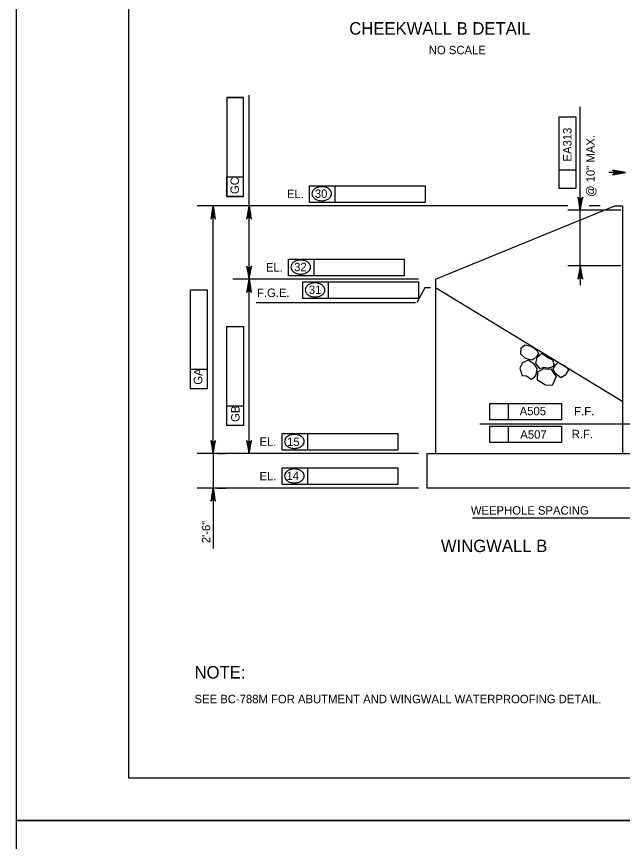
# Model space of a CAD drawing. Extents: x 638340 to 640242, y 295465 to 298435.
# Drawn here: x 638435.5 to 638651, y 296646 to 296939.5 of the extents above; entities that cross this region are included whole.
import ezdxf

# ---------------------------------------------------------------- set-up
doc = ezdxf.new("R2010")
doc.units = 0
for name, color, linetype in [('1', 7, 'Continuous'), ('2', 7, 'Continuous'), ('3', 7, 'Continuous'), ('4', 7, 'Continuous'), ('Level 10', 7, 'Continuous'), ('Level 3', 7, 'Continuous'), ('Level 4', 7, 'Continuous'), ('PLT-BNDY', 7, 'Continuous')]:
    doc.layers.add(name, color=color, linetype=linetype)

# ---------------------------------------------------------------- blocks, each defined once
blk = doc.blocks.new('ROCK')
at = {"layer": '4'}
for points in [[(2.36725, 1.088), (2.2065, 0.82625), (2.378625, 0.506625), (2.66975, 0.3095), (3.128875, 0.403375), (3.48475, 0.6775), (3.4915, 1.123375), (3.25625, 1.36725), (2.783625, 1.308375)], [(1.10175, -0.02725), (1.4015, -0.159125), (1.78825, -0.148875), (1.980875, -0.266), (2.343375, 0.09475), (2.27875, 0.5505), (1.969375, 0.883), (1.4225, 0.553625), (1.152875, 0.479), (1.0105, 0.082)], [(0.74675, 0.359875), (0.882, 0.16), (1.072875, -0.144), (0.892, -0.457375), (0.448125, -0.758625), (0.1, -0.49325), (-0.095, -0.146375), (0.202875, 0.1025), (0.579125, 0.219875)], [(2.231375, -0.71725), (2.2025, -0.266375), (2.45475, 0.037125), (2.9085, 0.28875), (3.2995, 0.047625), (3.46875, -0.344), (3.231625, -0.855), (2.92, -0.860375), (2.5765, -1.054625), (2.340375, -0.904375)], [(1.2085, -0.192875), (0.778375, -0.737625), (1.008375, -1.391375), (1.48725, -1.396875), (2.09825, -1.106625), (2.133375, -0.486375), (1.723125, -0.203375), (1.37425, -0.239875)]]:
    blk.add_lwpolyline(points, close=True, dxfattribs=at)
blk = doc.blocks.new('V')
at = {"layer": '1'}
blk.add_line((0, 0), (0, 0), dxfattribs=at)

msp = doc.modelspace()

# ---------------------------------------------------------------- linework, layer by layer
at = {"layer": '2'}
for p, q in [((638475.46, 296668.46), (638475.46, 297232.46)), ((639261.46, 296668.46), (638475.46, 296668.46))]:
    msp.add_line(p, q, dxfattribs=at)
at = {"layer": 'Level 10'}
for p, q in [((638584.47, 296845.97), (638648.28, 296872.06)), ((638648.28, 296872.06), (638650.94, 296872.06)), ((638650.94, 296872.06), (638650.94, 296783.96)), ((638584.47, 296845.97), (638584.47, 296783.96)), ((638651.16, 296802.37), (638584.47, 296842.9)), ((638581.4, 296783.96), (638729.24, 296783.96)), ((638581.4, 296783.96), (638581.4, 296771.68)), ((638961.9, 296771.68), (638581.4, 296771.68))]:
    msp.add_line(p, q, dxfattribs=at)
at = {"layer": 'Level 3'}
for p, q in [((638510.32, 296910.64), (638510.32, 296875.4)), ((638516.22, 296910.64), (638510.32, 296910.64)), ((638510.32, 296910.64), (638516.22, 296910.64)), ((638516.22, 296882.24), (638516.22, 296910.64)), ((638516.22, 296903.81), (638516.22, 296910.64)), ((638518.18, 296845.97), (638518.18, 296911.47)), ((638635.97, 296870.53), (638635.97, 296907.31)), ((638628.45, 296878.25), (638628.45, 296903.74)), ((638628.45, 296903.74), (638634.35, 296903.74)), ((638634.35, 296903.74), (638634.35, 296878.25)), ((638634.35, 296884.83), (638628.45, 296884.83)), ((638652.09, 296883.97), (638646.18, 296883.97)), ((638510.32, 296875.4), (638510.32, 296882.24)), ((638516.22, 296882.24), (638510.32, 296882.24)), ((638516.22, 296875.4), (638516.22, 296882.24)), ((638539.65, 296879.24), (638548.81, 296879.24)), ((638539.65, 296873.34), (638539.65, 296879.24)), ((638548.81, 296873.34), (638548.81, 296879.24)), ((638548.81, 296879.24), (638580.78, 296879.24)), ((638580.78, 296879.24), (638580.78, 296873.34)), ((638634.35, 296878.25), (638628.45, 296878.25)), ((638510.32, 296875.4), (638516.22, 296875.4)), ((638516.22, 296875.4), (638510.32, 296875.4)), ((638635.97, 296873.47), (638635.97, 296876.42)), ((638631.58, 296872.06), (638499.66, 296872.06)), ((638506.51, 296872.06), (638501, 296872.06)), ((638511.74, 296872.06), (638501, 296872.06)), ((638505.42, 296783.96), (638505.42, 296872.06)), ((638520.64, 296872.06), (638513.76, 296872.06)), ((638580.78, 296873.34), (638539.65, 296873.34)), ((638643.03, 296872.06), (638639.11, 296872.06)), ((638650.4, 296870.53), (638631.55, 296870.53)), ((638635.97, 296849.77), (638635.97, 296870.53)), ((638532.17, 296853.14), (638541.32, 296853.14)), ((638532.17, 296847.25), (638532.17, 296853.14)), ((638541.32, 296847.25), (638541.32, 296853.14)), ((638541.32, 296853.14), (638573.3, 296853.14)), ((638573.3, 296853.14), (638573.3, 296847.25)), ((638650.4, 296850.7), (638631.55, 296850.7)), ((638635.97, 296849.77), (638635.97, 296843.88)), ((638578.42, 296845.97), (638512.41, 296845.97)), ((638523.52, 296845.97), (638513.76, 296845.97)), ((638518.18, 296783.96), (638518.18, 296845.97)), ((638573.3, 296847.25), (638532.17, 296847.25)), ((638537.28, 296845.01), (638546.43, 296845.01)), ((638537.28, 296839.12), (638537.28, 296845.01)), ((638546.43, 296839.12), (638546.43, 296845.01)), ((638546.43, 296845.01), (638578.41, 296845.01)), ((638578.41, 296845.01), (638578.41, 296839.12)), ((638497.38, 296842.24), (638503.28, 296842.24)), ((638497.38, 296813.84), (638497.38, 296842.24)), ((638503.28, 296842.24), (638503.28, 296807.01)), ((638580.65, 296842.9), (638577.88, 296837.71)), ((638578.41, 296839.12), (638537.28, 296839.12)), ((638520.66, 296837.71), (638577.35, 296837.71)), ((638510.28, 296829.2), (638516.17, 296829.2)), ((638510.28, 296800.79), (638510.28, 296829.2)), ((638516.17, 296829.2), (638516.17, 296793.96)), ((638497.38, 296807.01), (638497.38, 296813.84)), ((638503.28, 296813.84), (638497.38, 296813.84)), ((638503.28, 296807.01), (638497.38, 296807.01)), ((638510.28, 296793.96), (638510.28, 296800.79)), ((638516.17, 296800.79), (638510.28, 296800.79)), ((638603.82, 296801.82), (638629.31, 296801.82)), ((638603.82, 296795.93), (638603.82, 296801.82)), ((638610.4, 296795.93), (638610.4, 296801.82)), ((638629.31, 296801.82), (638629.31, 296795.93)), ((638629.31, 296795.93), (638603.82, 296795.93)), ((638516.17, 296793.96), (638510.28, 296793.96)), ((638600.3, 296794.53), (638662, 296794.53)), ((638603.82, 296787.86), (638603.82, 296793.76)), ((638603.82, 296793.76), (638629.31, 296793.76)), ((638610.4, 296787.86), (638610.4, 296793.76)), ((638629.31, 296793.76), (638629.31, 296787.86)), ((638529.91, 296791.13), (638539.07, 296791.13)), ((638529.91, 296785.23), (638529.91, 296791.13)), ((638539.07, 296785.23), (638539.07, 296791.13)), ((638539.07, 296791.13), (638571.04, 296791.13)), ((638571.04, 296791.13), (638571.04, 296785.23)), ((638629.31, 296787.86), (638603.82, 296787.86)), ((638578.42, 296783.96), (638499.66, 296783.96)), ((638506.51, 296783.96), (638501, 296783.96)), ((638506.98, 296783.96), (638501, 296783.96)), ((638511.74, 296783.96), (638501, 296783.96)), ((638505.42, 296783.96), (638505.42, 296771.68)), ((638506.89, 296783.96), (638509.84, 296783.96)), ((638571.04, 296785.23), (638529.91, 296785.23)), ((638529.91, 296772.96), (638529.91, 296778.85)), ((638529.91, 296778.85), (638539.07, 296778.85)), ((638539.07, 296772.96), (638539.07, 296778.85)), ((638539.07, 296778.85), (638571.04, 296778.85)), ((638571.04, 296778.85), (638571.04, 296772.96)), ((638578.42, 296771.68), (638499.66, 296771.68)), ((638505.42, 296771.68), (638505.42, 296750.18)), ((638506.89, 296771.68), (638509.84, 296771.68)), ((638571.04, 296772.96), (638529.91, 296772.96)), ((638883.14, 296760.94), (638597.64, 296760.94))]:
    msp.add_line(p, q, dxfattribs=at)
for points in [[(638652.09, 296883.97), (638647.44, 296884.84), (638647.8, 296884.6), (638647.98, 296884.29), (638648.03, 296883.97), (638647.98, 296883.66), (638647.8, 296883.35), (638647.44, 296883.1), (638652.09, 296883.97), (638647.8, 296883.35), (638647.98, 296883.66), (638652.09, 296883.97), (638648.03, 296883.97), (638647.98, 296884.29), (638652.09, 296883.97), (638647.8, 296884.6)], [(638635.97, 296870.53), (638636.84, 296875.18), (638636.6, 296874.82), (638636.28, 296874.64), (638635.97, 296874.58), (638635.66, 296874.64), (638635.35, 296874.82), (638635.1, 296875.18), (638635.97, 296870.53), (638635.35, 296874.82), (638635.66, 296874.64), (638635.97, 296870.53), (638635.97, 296874.58), (638636.28, 296874.64), (638635.97, 296870.53), (638636.6, 296874.82)], [(638505.42, 296872.06), (638504.55, 296867.41), (638504.8, 296867.77), (638505.11, 296867.95), (638505.42, 296868.01), (638505.73, 296867.95), (638506.04, 296867.77), (638506.29, 296867.41), (638505.42, 296872.06), (638506.04, 296867.77), (638505.73, 296867.95), (638505.42, 296872.06), (638505.42, 296868.01), (638505.11, 296867.95), (638505.42, 296872.06), (638504.8, 296867.77)], [(638518.18, 296872.06), (638517.31, 296867.41), (638517.56, 296867.77), (638517.87, 296867.95), (638518.18, 296868.01), (638518.49, 296867.95), (638518.8, 296867.77), (638519.05, 296867.41), (638518.18, 296872.06), (638518.8, 296867.77), (638518.49, 296867.95), (638518.18, 296872.06), (638518.18, 296868.01), (638517.87, 296867.95), (638518.18, 296872.06), (638517.56, 296867.77)], [(638518.18, 296845.97), (638519.05, 296850.62), (638518.8, 296850.26), (638518.49, 296850.08), (638518.18, 296850.02), (638517.87, 296850.08), (638517.56, 296850.26), (638517.31, 296850.62), (638518.18, 296845.97), (638517.56, 296850.26), (638517.87, 296850.08), (638518.18, 296845.97), (638518.18, 296850.02), (638518.49, 296850.08), (638518.18, 296845.97), (638518.8, 296850.26)], [(638635.97, 296850.7), (638635.1, 296846.05), (638635.35, 296846.41), (638635.66, 296846.59), (638635.97, 296846.64), (638636.28, 296846.59), (638636.6, 296846.41), (638636.84, 296846.05), (638635.97, 296850.7), (638636.6, 296846.41), (638636.28, 296846.59), (638635.97, 296850.7), (638635.97, 296846.64), (638635.66, 296846.59), (638635.97, 296850.7), (638635.35, 296846.41)], [(638518.18, 296845.97), (638517.31, 296841.32), (638517.56, 296841.67), (638517.87, 296841.86), (638518.18, 296841.91), (638518.49, 296841.86), (638518.8, 296841.67), (638519.05, 296841.32), (638518.18, 296845.97), (638518.8, 296841.67), (638518.49, 296841.86), (638518.18, 296845.97), (638518.18, 296841.91), (638517.87, 296841.86), (638518.18, 296845.97), (638517.56, 296841.67)], [(638505.42, 296783.96), (638506.29, 296788.61), (638506.04, 296788.25), (638505.73, 296788.06), (638505.42, 296788.01), (638505.11, 296788.06), (638504.8, 296788.25), (638504.55, 296788.61), (638505.42, 296783.96), (638504.8, 296788.25), (638505.11, 296788.06), (638505.42, 296783.96), (638505.42, 296788.01), (638505.73, 296788.06), (638505.42, 296783.96), (638506.04, 296788.25)], [(638518.18, 296783.96), (638519.05, 296788.61), (638518.8, 296788.25), (638518.49, 296788.06), (638518.18, 296788.01), (638517.87, 296788.06), (638517.56, 296788.25), (638517.31, 296788.61), (638518.18, 296783.96), (638517.56, 296788.25), (638517.87, 296788.06), (638518.18, 296783.96), (638518.18, 296788.01), (638518.49, 296788.06), (638518.18, 296783.96), (638518.8, 296788.25)], [(638505.42, 296771.68), (638504.55, 296767.03), (638504.8, 296767.38), (638505.11, 296767.57), (638505.42, 296767.62), (638505.73, 296767.57), (638506.04, 296767.38), (638506.29, 296767.03), (638505.42, 296771.68), (638506.04, 296767.38), (638505.73, 296767.57), (638505.42, 296771.68), (638505.42, 296767.62), (638505.11, 296767.57), (638505.42, 296771.68), (638504.8, 296767.38)]]:
    msp.add_lwpolyline(points, dxfattribs=at)
for points in [[(638649.12, 296884.46), (638649.12, 296883.48), (638652.07, 296883.97)], [(638505.91, 296869.12), (638504.93, 296869.12), (638505.42, 296872.06)], [(638518.67, 296869.12), (638517.69, 296869.12), (638518.18, 296872.06)], [(638636.47, 296873.47), (638635.48, 296873.47), (638635.97, 296870.53)], [(638518.67, 296848.92), (638517.69, 296848.92), (638518.18, 296845.97)], [(638518.67, 296843.02), (638517.69, 296843.02), (638518.18, 296845.97)], [(638505.91, 296786.9), (638504.93, 296786.9), (638505.42, 296783.96)], [(638518.67, 296786.9), (638517.69, 296786.9), (638518.18, 296783.96)], [(638505.91, 296768.73), (638504.93, 296768.73), (638505.42, 296771.68)]]:
    msp.add_lwpolyline(points, close=True, dxfattribs=at)
for centre, radius, start, end in [((638542.35, 296876.4), 1.82, 149.9767, 180), ((638543.15, 296875.93), 2.75, 125.6316, 149.9767), ((638543.68, 296875.2), 3.65, 106.5358, 125.6316), ((638544.02, 296874.04), 4.86, 90, 106.5358), ((638544.02, 296874.04), 4.86, 73.4642, 90), ((638544.36, 296875.2), 3.65, 54.3684, 73.4642), ((638544.89, 296875.93), 2.75, 30.0233, 54.3684), ((638545.69, 296876.4), 1.82, 0, 30.0233), ((638542.35, 296876.4), 1.82, 180, 210.0233), ((638543.15, 296876.86), 2.75, 210.0233, 234.3684), ((638543.68, 296877.59), 3.65, 234.3684, 253.4642), ((638544.36, 296877.59), 3.65, 286.5358, 305.6316), ((638544.89, 296876.86), 2.75, 305.6316, 329.9767), ((638545.69, 296876.4), 1.82, 329.9767, 0), ((638544.02, 296878.75), 4.86, 253.4642, 270), ((638544.02, 296878.75), 4.86, 270, 286.5358), ((638534.86, 296850.3), 1.82, 149.9767, 180), ((638535.67, 296849.84), 2.75, 125.6316, 149.9767), ((638536.19, 296849.1), 3.65, 106.5358, 125.6316), ((638536.54, 296847.95), 4.86, 90, 106.5358), ((638536.54, 296847.95), 4.86, 73.4642, 90), ((638536.88, 296849.1), 3.65, 54.3684, 73.4642), ((638537.41, 296849.84), 2.75, 30.0233, 54.3684), ((638538.21, 296850.3), 1.82, 0, 30.0233), ((638534.86, 296850.3), 1.82, 180, 210.0233), ((638535.67, 296850.77), 2.75, 210.0233, 234.3684), ((638536.19, 296851.5), 3.65, 234.3684, 253.4642), ((638536.54, 296852.66), 4.86, 253.4642, 270), ((638536.54, 296852.66), 4.86, 270, 286.5358), ((638536.88, 296851.5), 3.65, 286.5358, 305.6316), ((638537.41, 296850.77), 2.75, 305.6316, 329.9767), ((638538.21, 296850.3), 1.82, 329.9767, 0), ((638539.97, 296842.18), 1.82, 149.9767, 180), ((638539.97, 296842.18), 1.82, 180, 210.0233), ((638540.78, 296841.71), 2.75, 125.6316, 149.9767), ((638541.3, 296840.98), 3.65, 106.5358, 125.6316), ((638541.65, 296839.82), 4.86, 90, 106.5358), ((638541.65, 296839.82), 4.86, 73.4642, 90), ((638541.99, 296840.98), 3.65, 54.3684, 73.4642), ((638542.52, 296841.71), 2.75, 30.0233, 54.3684), ((638543.32, 296842.18), 1.82, 0, 30.0233), ((638543.32, 296842.18), 1.82, 329.9767, 0), ((638540.78, 296842.64), 2.75, 210.0233, 234.3684), ((638541.3, 296843.37), 3.65, 234.3684, 253.4642), ((638541.65, 296844.53), 4.86, 253.4642, 270), ((638541.65, 296844.53), 4.86, 270, 286.5358), ((638541.99, 296843.37), 3.65, 286.5358, 305.6316), ((638542.52, 296842.64), 2.75, 305.6316, 329.9767), ((638532.61, 296788.29), 1.82, 149.9767, 180), ((638533.41, 296787.83), 2.75, 125.6316, 149.9767), ((638533.94, 296787.09), 3.65, 106.5358, 125.6316), ((638534.28, 296785.93), 4.86, 90, 106.5358), ((638534.28, 296785.93), 4.86, 73.4642, 90), ((638534.63, 296787.09), 3.65, 54.3684, 73.4642), ((638535.15, 296787.83), 2.75, 30.0233, 54.3684), ((638535.96, 296788.29), 1.82, 0, 30.0233), ((638532.61, 296788.29), 1.82, 180, 210.0233), ((638533.41, 296788.75), 2.75, 210.0233, 234.3684), ((638533.94, 296789.49), 3.65, 234.3684, 253.4642), ((638534.63, 296789.49), 3.65, 286.5358, 305.6316), ((638535.15, 296788.75), 2.75, 305.6316, 329.9767), ((638535.96, 296788.29), 1.82, 329.9767, 0), ((638534.28, 296790.65), 4.86, 253.4642, 270), ((638534.28, 296790.65), 4.86, 270, 286.5358), ((638533.41, 296775.55), 2.75, 125.6316, 149.9767), ((638533.94, 296774.81), 3.65, 106.5358, 125.6316), ((638534.28, 296773.65), 4.86, 90, 106.5358), ((638534.28, 296773.65), 4.86, 73.4642, 90), ((638534.63, 296774.81), 3.65, 54.3684, 73.4642), ((638535.15, 296775.55), 2.75, 30.0233, 54.3684), ((638532.61, 296776.01), 1.82, 149.9767, 180), ((638532.61, 296776.01), 1.82, 180, 210.0233), ((638533.41, 296776.47), 2.75, 210.0233, 234.3684), ((638535.15, 296776.47), 2.75, 305.6316, 329.9767), ((638535.96, 296776.01), 1.82, 0, 30.0233), ((638535.96, 296776.01), 1.82, 329.9767, 0), ((638533.94, 296777.21), 3.65, 234.3684, 253.4642), ((638534.28, 296778.37), 4.86, 253.4642, 270), ((638534.28, 296778.37), 4.86, 270, 286.5358), ((638534.63, 296777.21), 3.65, 286.5358, 305.6316)]:
    msp.add_arc(centre, radius, start, end, dxfattribs=at)
at = {"layer": 'Level 4'}
msp.add_line((638582.71, 296842.9), (638580.65, 296842.9), dxfattribs=at)
at = {"layer": 'PLT-BNDY'}
for points in [[(638435.46, 297247.46), (639276.46, 297247.46), (639276.46, 296653.46), (638435.46, 296653.46)], [(638435.46, 296653.46), (639276.46, 296653.46), (639276.46, 296059.46), (638435.46, 296059.46)]]:
    msp.add_lwpolyline(points, close=True, dxfattribs=at)

# ---------------------------------------------------------------- block references
at = {"layer": 'Level 3', "xscale": 4.9118761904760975, "yscale": -4.911876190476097, "rotation": 174.84722800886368}
msp.add_blockref('ROCK', (638631.55, 296814.51), dxfattribs=at)
at = {"layer": 'Level 3', "xscale": 0.7859001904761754, "yscale": 0.7859001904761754}
msp.add_blockref('V', (638555.55, 296778.71), dxfattribs=at)

# ---------------------------------------------------------------- texts
at = {"layer": '2'}
msp.add_text('SEE BC-788M FOR ABUTMENT AND WINGWALL WATERPROOFING DETAIL.', height=3.0001, dxfattribs=at).set_placement((638498.79, 296695.14))
at = {"layer": '3'}
for s, height, p in [('CHEEKWALL B DETAIL', 4.4294, (638553.82, 296933.01)), ('NO SCALE', 3, (638582.11, 296926.03)), ('WINGWALL B', 4.429, (638586.4, 296748.91))]:
    msp.add_text(s, height=height, dxfattribs=at).set_placement(p)
at = {"layer": '4'}
msp.add_text('NOTE:', height=4.429, dxfattribs=at).set_placement((638498.79, 296703.94))
at = {"layer": 'Level 3'}
for s, p in [('EA313', (638632.85, 296887.87)), ('@ 10" MAX.', (638641.12, 296875.28)), ('GC', (638514.57, 296876.29)), ('GA', (638501.53, 296808.46)), ('GB', (638514.8, 296795.23)), ('2\'-6"', (638504.38, 296752.08))]:
    msp.add_text(s, height=3, rotation=90, dxfattribs=at).set_placement(p)
for s, height, p in [('EL.', 3, (638531.65, 296874.83)), ('30', 3, (638541.56, 296874.94)), ('EL.', 3, (638524.17, 296848.73)), ('32', 3, (638534.19, 296848.85)), ('F.G.E.', 3, (638520.99, 296839.66)), ('31', 3, (638539.43, 296840.72)), ('A505', 3, (638614.42, 296797.58)), ('F.F.', 3, (638633.81, 296797.55)), ('A507', 3, (638614.66, 296789.25)), ('R.F.', 3, (638632.94, 296789.42)), ('EL.', 3, (638521.91, 296786.72)), ('15', 3, (638531.69, 296786.64)), ('EL.', 3, (638521.91, 296774.44)), ('14', 3, (638531.48, 296774.55)), ('WEEPHOLE SPACING', 3.0001, (638597.06, 296762.24))]:
    msp.add_text(s, height=height, dxfattribs=at).set_placement(p)

doc.saveas('drawing.dxf')
